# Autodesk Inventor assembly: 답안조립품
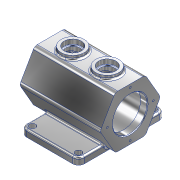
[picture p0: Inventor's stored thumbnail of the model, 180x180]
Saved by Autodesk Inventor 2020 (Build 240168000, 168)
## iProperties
Created: 2021-06
Part Number: 답안조립품
Document SubType Name: Assembly
Designer: Administrator
Author: Administrator
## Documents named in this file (2)
- C:\Users\Administrator\Desktop\710606V1007\답안조립품.iam
- C:\Users\Administrator\Desktop\710606V1007\본체.ipt
